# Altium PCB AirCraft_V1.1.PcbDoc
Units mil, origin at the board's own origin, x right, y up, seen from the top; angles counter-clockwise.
Board outline 935 x 623 mil, 2 copper layers (Top Layer, Bottom Layer); 13 components, 14 nets, 58 pads, 9 vias.
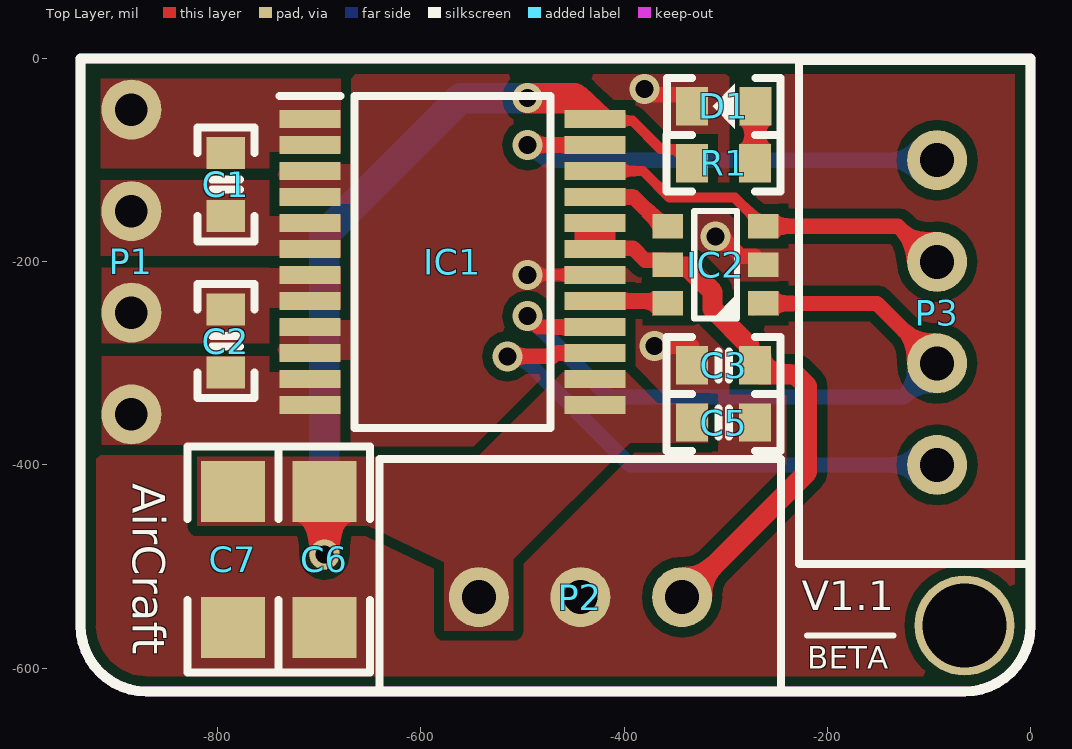
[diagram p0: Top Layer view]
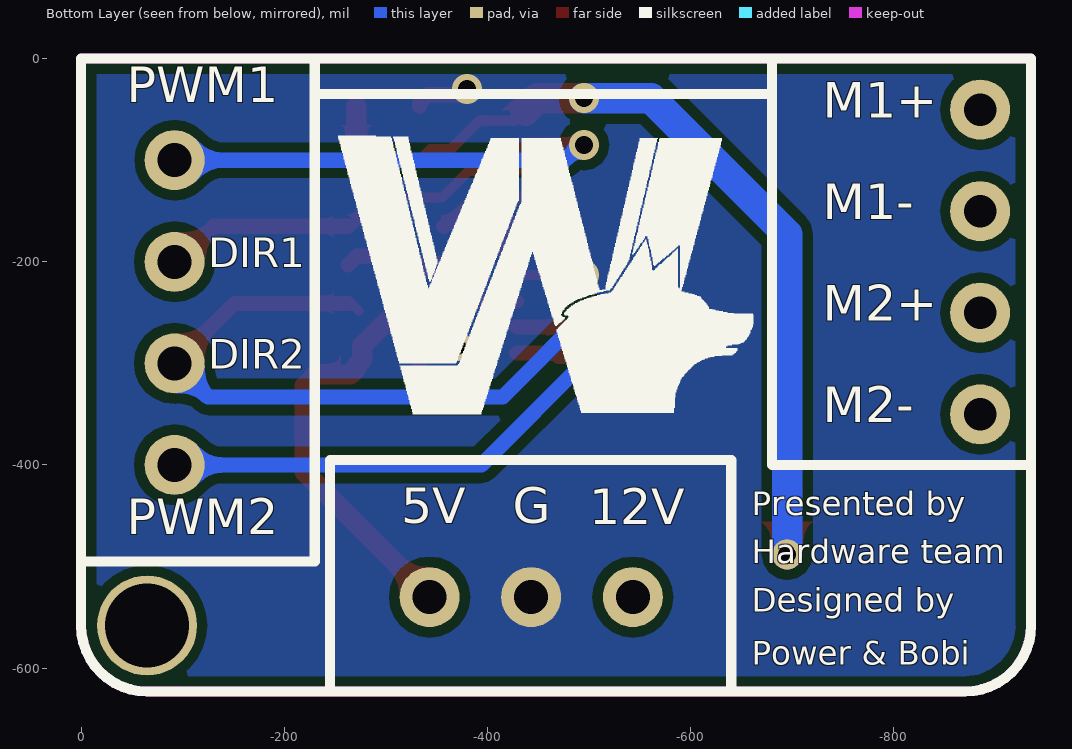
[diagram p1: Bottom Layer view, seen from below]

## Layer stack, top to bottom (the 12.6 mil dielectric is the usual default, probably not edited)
Top Solder: solder mask 0.4, Solder Resist, Dk 3.5
Top Layer: signal copper 1.4
Dielectric 1: dielectric 12.6, FR-4, Dk 4.8
Bottom Layer: signal copper 1.4
Bottom Solder: solder mask 0.4, Solder Resist, Dk 3.5

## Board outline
-935,-558 ccw(c-870,-558) -870,-623 -65,-623 ccw(c-65,-558) 0,-558 0,0 -935,0

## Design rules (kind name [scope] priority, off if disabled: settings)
Clearance [All] p1: gap=10 ignorepadtopadclearanceinfootprint=FALSE except(0: Arc-Hole Track-Hole SMDPad-Hole THPad-Hole Via-Hole Fill-Hole Poly-Hole Region-Hole Text-Hole)
PlaneConnect [All] p1: planeconnectstyle=Direct reliefexpansion=20 reliefentries=4 reliefconductorwidth=10 reliefairgap=10
PolygonConnect [All] p1: connectstyle=Direct reliefconductorwidth=10 reliefentries=4 polygonreliefangle="90 Angle" airgapwidth=10
RoomDefinition AirCraft_V1.0 [InComponentClass('AirCraft_V1.0')] p1: confinementstyle=ConfineIn formatcopy=TRUE lockcomponents=FALSE outline -6530,-3227 -4530,-3227 -4530,-2227 -6530,-2227
RoutingVias [All] p1: holewidth=17.72 width=29.53 viastyle="Through Hole" minholewidth=17.72 minwidth=29.53 maxholewidth=17.72 maxwidth=29.53
SolderMaskExpansion [All] p1: expansion=4 istentingtop=FALSE
Width [All] p1: maxlimit=50 minlimit=10 preferedwidth=15
29 further rules are at their usual default settings.

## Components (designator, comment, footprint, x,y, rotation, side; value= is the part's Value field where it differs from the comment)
C1 "100nF" CAP-0603 -792,-123.9 r90 top
C2 "100nF" CAP-0603 -792,-278.1 r90 top
C3 "100nF" CAP-0603 -302.1,-302 r0 top
C5 "100nF" CAP-0603 -302.1,-358.22 r180 top
C6 "47uF" CAP-1206 -695,-492.93 r90 top
C7 "47uF" CAP-1206 -785,-492.93 r90 top
D1 "RED" LED-0603 -302,-47 r180 top
IC1 "TB6612FNG" SSOP24 -568.91,-200.16 r0 top locked
IC2 "SN74LVC2G14DBV" SOT-23-6 -310,-203 r0 top locked
P1 "HDR1x4_2.54" HDR1X4_2.54_90 -884.95,-350.16 r180 top locked
P2 "XH-3AW" XH_3 -443,-530 r0 top locked
P3 "XH-4AW" XH_4 -92.03,-250 r90 top locked
R1 "4.7k" R-0603 -302.1,-103 r180 top

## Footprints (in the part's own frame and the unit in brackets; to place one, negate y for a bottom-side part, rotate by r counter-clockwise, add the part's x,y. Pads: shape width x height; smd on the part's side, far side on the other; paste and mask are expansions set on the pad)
CAP-0603 [mm]
  rect 0.8x0.96 smd: 1(-0.79,0) 2(0.79,0)
  silkscreen extent -1.42,-0.71 1.42,0.71, body extent -0.76,-0.39 0.76,0.39, height 0.9
CAP-1206 [mm] "贴片元件"
  rect 1.524x1.6 smd: 1(-1.703,0) 2(1.7,0)
  silkscreen extent -2.83,-1.14 2.83,1.14, body extent -1.91,-0.89 1.91,0.89, height 1
HDR1X4_2.54_90 [mm]
  round 1.5 hole 0.813: 1(0,0) 2(0,-2.54) 3(0,-5.08) 4(0,-7.62)
  body extent -0.38,-8.79 10.76,1.17, height 2.52
LED-0603 [mm]
  rect 0.8x0.96 smd: 1(-0.79,0) 2(0.79,0)
  silkscreen extent -1.42,-0.71 1.42,0.71, body extent -0.81,-0.4 0.81,0.4, height 0.6
R-0603 [mm]
  rect 0.8x0.96 smd: 1(-0.79,0) 2(0.79,0)
  silkscreen extent -1.42,-0.71 1.42,0.71, body extent -0.76,-0.38 0.76,0.38, height 0.41
SOT-23-6 [mil]
  rect 30x24 smd: 1(47,-38) 2(47,0) 3(47,38) 4(-47,38) 5(-47,0) 6(-47,-38)
  silkscreen extent -21,-53 21,53, body extent -55,-57 55,57, height 57
SSOP24 [mm]
  rect 1.525x0.45 smd: 1(-3.562,3.575) 2(-3.562,2.925) 3(-3.562,2.275) 4(-3.562,1.625) 5(-3.562,0.975) 6(-3.562,0.325) 7(-3.562,-0.325) 8(-3.562,-0.975) 9(-3.562,-1.625) 10(-3.562,-2.275) 11(-3.562,-2.925) 12(-3.562,-3.575) 13(3.562,-3.575) 14(3.562,-2.925) 15(3.562,-2.275) 16(3.562,-1.625) 17(3.562,-0.975) 18(3.562,-0.325) 19(3.562,0.325) 20(3.562,0.975) 21(3.562,1.625) 22(3.562,2.275) 23(3.562,2.925) 24(3.562,3.575)
  silkscreen extent -4.33,-4.15 2.45,4.15, body extent -3.8,-4.15 3.8,4.15, height 1.6
XH_3 [mm]
  round 1.5 hole 0.85: 1(-2.54,0) 2(0,0) 3(2.54,0)
  silkscreen extent -5.02,-2.35 5.02,3.45, body extent -5.02,-2.35 5.02,3.45, height 7.21
XH_4 [mm]
  round 1.5 hole 0.85: 1(-3.81,0) 2(-1.27,0) 3(1.27,0) 4(3.81,0)
  silkscreen extent -6.29,-2.35 6.29,3.45, body extent -6.29,-2.35 6.29,3.45, height 7.2

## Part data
C1 C2 C3 C5 C6 C7: library part CAP, "贴片电容", Package=0402, SuppliersPartNumber=C52923
D1: library part LED, "发光二极管", Package=0603, SuppliersPartNumber=C2290
IC1: "集成电机驱动芯片", Manufacturer_Name=Toshiba, Manufacturer_Part_Number=TB6612FNG(O,EL), Mouser Part Number=757-TB6612FNG(O,EL)
IC2: "变换器", Arrow Part Number=SN74LVC2G14DBVR, Manufacturer_Name="Texas Instruments", Mouser Part Number=595-SN74LVC2G14DBVR
P1: "Header"
P2: library part HDR1x3_2.54, "Header"
P3: library part HDR1x4_2.54, "Header"
R1: library part RES, "贴片电阻", Package=0805, SuppliersPartNumber=C17798

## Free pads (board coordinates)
  round 98.43 hole 82.68: 1(-65,-558)

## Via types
v1: diameter 29.53, hole 17.72, Top Layer to Bottom Layer, 9 vias

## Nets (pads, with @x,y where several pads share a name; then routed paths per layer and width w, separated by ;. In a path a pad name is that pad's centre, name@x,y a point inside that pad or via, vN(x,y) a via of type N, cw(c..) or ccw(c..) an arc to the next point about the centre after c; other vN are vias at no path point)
5V: C3.2 IC1.19 IC1.20 IC2.5 P2.3 | length 550.4
  Top Layer w15: -428.68,-176 -428.68,-177.81 -419.89,-186.6 -391.41,-186.6 -379.51,-198.5 -361.5,-198.5 IC2.5
  Top Layer w20: IC2.5 -355,-205 -337.72,-205 -313,-229.72 -313,-246.28 -276.75,-282.54 -276.75,-296.25 C3.2 -271,-305.15 -265.25,-310.9 -231.72,-310.9 -220,-322.61 -220,-407 P2.3
  Top Layer w40: -428.68,-176 -428.68,-174
12V: C5.2 C6.2 C7.2 IC1.13 IC1.14 IC1.24 P2.1 R1.2 | length 808.5
  Top Layer w10: IC1.24@-426.94,-61.15 -391.85,-61.15 -363.9,-89.1 -343.95,-89.1 -333.2,-99.85 R1.2
  Top Layer w30: v1(-695,-488) C6.2 ; v1(-495,-39) -449.09,-39 IC1.24@-436.94,-51.15
  Bottom Layer w30: v1(-695,-488) -695,-173 -561,-39 v1(-495,-39)
DIR1: IC1.22 IC2.3 P3.3 | length 375.4
  Top Layer w10: IC1.22 -381.47,-110.6 -355.17,-136.9 -291.1,-136.9 -273,-155 -273,-158 -266,-165 IC2.3
  Top Layer w15: IC2.3 -130.61,-165 -95.61,-200 P3.3
DIR2: IC1.16 IC2.1 P3.2 | length 728.6
  Top Layer w10: IC2.1@-273,-248 -266,-241 IC2.1
  Top Layer w15: v1(-495,-253.47) -484.33,-264.14 IC1.16 ; IC2.1 -151.03,-241 P3.2
  Bottom Layer w15: v1(-495,-253.47) -494.53,-253.47 -415,-333 -125.03,-333 P3.2
GND: C3.1 C5.1 C6.1 C7.1 D1.2 IC1.3 IC1.4 IC1.9 IC1.10 IC1.18 IC2.2 P2.2 | length 236.6
  Top Layer w10: v1(-495,-212.96) IC1.18
  Top Layer w15: v1(-380,-29.76) -376.07,-29.76 -370.23,-35.6 -341.35,-35.6 -333.1,-43.85 D1.2 ; v1(-370,-283) -333.2,-283 C3.1 ; v1(-310,-175) -304.75,-175 -285.25,-194.5 -271.5,-194.5 IC2.2
NetC1_1: C1.1 IC1.5 IC1.6 P1.3
NetC1_2: C1.2 IC1.1 IC1.2 P1.4
NetC2_1: C2.1 IC1.11 IC1.12 P1.1
NetC2_2: C2.2 IC1.7 IC1.8 P1.2
NetD1_A: D1.1 R1.1 | length 56
  Top Layer w20: R1.1 -270.95,-102.95 -270.95,-47.05 D1.1
NetIC1_17: IC1.17 IC2.6 | length 72.7
  Top Layer w15: IC1.17 -359.45,-238.55 IC2.6
NetIC1_21: IC1.21 IC2.4 | length 83.6
  Top Layer w15: IC1.21 -390.64,-136.19 -366.33,-160.5 -361.5,-160.5 IC2.4
PWM1: IC1.23 P3.4 | length 475.5
  Top Layer w15: v1(-495,-85) IC1.23
  Bottom Layer w15: v1(-495,-85) -491.07,-85 -476.07,-100 P3.4
PWM2: IC1.15 P3.1 | length 555
  Top Layer w15: v1(-515,-293) -469.98,-293 -466.71,-289.73 IC1.15
  Bottom Layer w15: v1(-515,-293) -501.1,-293 -394.1,-400 P3.1

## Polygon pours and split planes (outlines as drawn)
GND on Top Layer "GND_L01_P013" (solid, remove dead copper, pour order 13): -1157,156 -1157,157 72,157 72,-760 -1128,-760
12V on Top Layer "12V_L01_P007" (solid, pour order 7): -820,-392 -820,-460 -652.24,-460 -577,-495.91 -577,-563 -509,-563 -509,-493 -394,-378 -317,-378 -317,-339 -367,-339 -399,-307 -459,-307 -544,-392
no net on Top Layer "NONET_L01_P004" (solid, pour order 4): -565,-553
NetC1_1 on Top Layer "NETC1_1_L01_P001" (solid, remove dead copper, pour order 1): -915,-120 -678.83,-120 -678.83,-194 -915,-194
NetC2_1 on Top Layer "NETC2_1_L01_P003" (solid, remove dead copper, pour order 3): -914,-293 -679.33,-293 -679.33,-380 -914,-380
NetC2_2 on Top Layer "NETC2_2_L01_P002" (solid, remove dead copper, pour order 2): -914.1,-206 -679.1,-206 -679.1,-280 -914.1,-280
NetC1_2 on Top Layer "NETC1_2_L01_P000" (solid, remove dead copper, pour order 0): -915,-20 -679,-20 -679,-108 -915,-108
GND on Bottom Layer "GND_L02_P014" (solid, remove dead copper, pour order 14): -1037,102 143,102 143,-772 -1047,-772

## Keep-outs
Keep-Out Layer:
  the board outline again, w10

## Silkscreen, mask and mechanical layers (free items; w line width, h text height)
Top Overlay:
  lines w6: -220,-568 -135,-568
  lines w10: -935,-558 ccw(c-870,-558) -870,-623 -65,-623 ccw(c-65,-558) 0,-558 0,0 -935,0 -935,-558
  text "AirCraft" at -894.43,-418 h55 r270
  text "V1.1" at -224.97,-553 h50
  text "BETA" at -220,-608 h38
Bottom Overlay:
  drawing of 1751 lines, arcs and shapes, not listed
  text "PWM1" at -45,-55 h60
  text "M1+" at -730,-70 h60
  text "M1-" at -730,-170 h60
  text "DIR1" at -125,-215 h50
  text "M2+" at -730,-270 h60
  text "DIR2" at -125,-315 h50
  text "M2-" at -730,-370 h60
  text "Presented by" at -660,-457.49 h40
  text "G" at -425,-469.38 h60
  text "5V" at -315,-469.38 h60
  text "12V" at -500,-470 h60
  text "PWM2" at -45,-480 h60
  text "Hardware team" at -660,-504.58 h40
  text "Designed by" at -660,-552.49 h40
  text "Power & Bobi" at -660,-604.42 h40
Mechanical 1:
  the board outline again, w10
